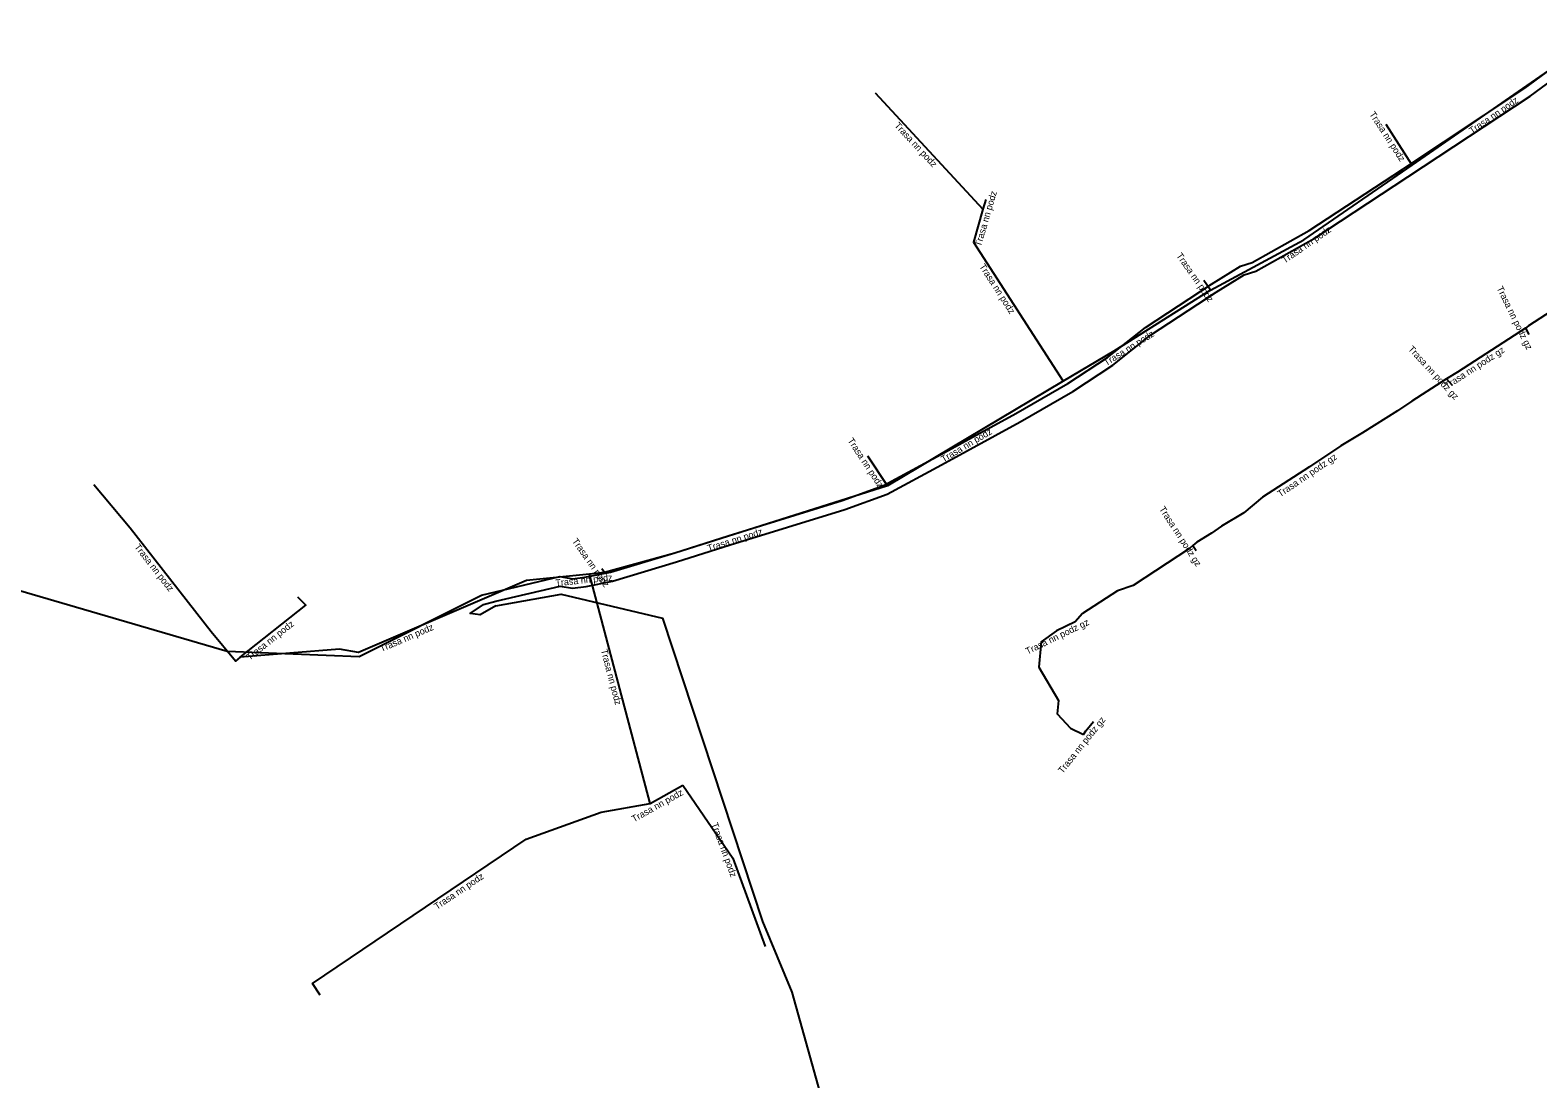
# Model space of a CAD drawing. Extents: x -711262 to -710488, y -1025222 to -1024810.
# Drawn here: x -711027.9 to -710915.5, y -1025074.1 to -1024995.9 of the extents above; entities that cross this region are included whole.
import ezdxf

# ---------------------------------------------------------------- set-up
doc = ezdxf.new("R2010")
doc.units = 0
for name, color, linetype in [('Popiskový text - Ostatní atributy Trasy', 7, 'Continuous'), ('Spojnice NN', 7, 'Continuous'), ('Spojnice VN', 7, 'Continuous')]:
    doc.layers.add(name, color=color, linetype=linetype)

msp = doc.modelspace()

# ---------------------------------------------------------------- linework, layer by layer
at = {"layer": 'Spojnice NN'}
for points in [[(-710924.81, -1025005.99), (-710911.47, -1024996.77)], [(-710964.86, -1025000.62), (-710956.82, -1025009.27)], [(-710924.81, -1025005.99), (-710926.76, -1025002.98)], [(-710939.85, -1025015.32), (-710932.89, -1025011.57), (-710924.81, -1025005.99)], [(-710899.11, -1025006.35), (-710900.09, -1025007.1), (-710905.35, -1025011.12), (-710905.55, -1025011.2), (-710906.97, -1025012.01), (-710911.93, -1025015.25), (-710916.14, -1025017.98), (-710916.36, -1025018.14)], [(-710956.61, -1025008.55), (-710956.82, -1025009.27)], [(-710956.82, -1025009.27), (-710957.52, -1025011.73), (-710950.83, -1025022.11)], [(-710939.85, -1025015.32), (-710947.06, -1025019.87), (-710950.83, -1025022.11)], [(-710939.85, -1025015.32), (-710940.35, -1025014.6)], [(-710916.36, -1025018.14), (-710921.45, -1025021.44), (-710922.25, -1025021.94)], [(-710916.36, -1025018.14), (-710916.12, -1025018.63)], [(-710950.83, -1025022.11), (-710963.95, -1025029.91)], [(-710922.25, -1025021.94), (-710924.84, -1025023.59), (-710925.92, -1025024.32), (-710928.52, -1025025.96), (-710930.15, -1025026.92), (-710932.47, -1025028.5), (-710935.98, -1025030.74), (-710937.37, -1025031.92), (-710939.03, -1025032.91), (-710939.77, -1025033.43), (-710940.87, -1025034.1), (-710941.17, -1025034.36)], [(-710922.25, -1025021.94), (-710921.84, -1025022.39)], [(-710963.95, -1025029.91), (-710965.4, -1025027.7)], [(-711012.21, -1025042.68), (-711012.54, -1025042.97), (-711014.37, -1025040.78), (-711020.41, -1025033.05), (-711023.11, -1025029.82)], [(-710963.95, -1025029.91), (-710979.79, -1025034.92), (-710985.05, -1025036.37)], [(-710941.17, -1025034.36), (-710941.41, -1025034.58), (-710945.61, -1025037.34), (-710946.8, -1025037.74), (-710949.41, -1025039.43), (-710949.95, -1025040.04), (-710951.33, -1025040.71), (-710952.48, -1025041.52), (-710952.65, -1025043.41), (-710951.2, -1025045.9), (-710951.29, -1025046.89), (-710950.3, -1025047.97), (-710949.32, -1025048.43)], [(-710941.17, -1025034.36), (-710940.93, -1025034.73)], [(-710986.15, -1025036.48), (-710990.85, -1025036.96), (-711003.39, -1025042.33), (-711004.79, -1025042.07), (-711012.21, -1025042.68)], [(-710985.05, -1025036.37), (-710986.15, -1025036.48)], [(-710981.63, -1025053.58), (-710986.15, -1025036.48)], [(-710985.05, -1025036.37), (-710985.24, -1025036.1)], [(-711012.21, -1025042.68), (-711007.3, -1025038.8), (-711007.89, -1025038.2)], [(-710949.32, -1025048.43), (-710949.14, -1025048.17), (-710948.58, -1025047.47)], [(-710981.63, -1025053.58), (-710979.19, -1025052.21)], [(-710979.19, -1025052.21), (-710975.46, -1025057.66), (-710973.06, -1025064.23)], [(-711006.23, -1025067.88), (-711006.82, -1025066.99), (-710990.88, -1025056.25), (-710985.29, -1025054.23), (-710981.63, -1025053.58)]]:
    msp.add_lwpolyline(points, dxfattribs=at)
at = {"layer": 'Spojnice VN'}
for points in [[(-710993.13, -1025038.86), (-710994.3, -1025039.53), (-710995.06, -1025039.43), (-710994.06, -1025038.74), (-710993.15, -1025038.51), (-710988.35, -1025037.39), (-710987.43, -1025037.53), (-710986.41, -1025037.41), (-710984.44, -1025037.01), (-710979.68, -1025035.58), (-710975.68, -1025034.3), (-710967.12, -1025031.66), (-710963.96, -1025030.52), (-710959.91, -1025028.34), (-710954.05, -1025025.14), (-710950.13, -1025022.88), (-710947.15, -1025020.92), (-710944.33, -1025018.68), (-710939.43, -1025015.48), (-710937.35, -1025014.18), (-710936.48, -1025013.91), (-710932.13, -1025011.48), (-710925.14, -1025006.88), (-710916.02, -1025000.85), (-710910.1, -1024996.5)], [(-710994.22, -1025038.06), (-710988.38, -1025036.67), (-710987.41, -1025036.83), (-710986.51, -1025036.72), (-710984.59, -1025036.33), (-710979.8, -1025034.89), (-710975.83, -1025033.62), (-710967.33, -1025030.99), (-710964.23, -1025029.88), (-710960.24, -1025027.71), (-710954.38, -1025024.52), (-710950.49, -1025022.28), (-710947.53, -1025020.33), (-710944.71, -1025018.09), (-710939.78, -1025014.87), (-710937.63, -1025013.52), (-710936.76, -1025013.26), (-710932.49, -1025010.88), (-710925.51, -1025006.29), (-710916.41, -1025000.27), (-710910.52, -1024995.94)], [(-711060.89, -1025028.3), (-711013.17, -1025042.23), (-711003.33, -1025042.63), (-710994.22, -1025038.06)], [(-710993.13, -1025038.86), (-710988.27, -1025037.98), (-710980.72, -1025039.77), (-710973.27, -1025062.38), (-710971.08, -1025067.64), (-710967.8, -1025079.41)]]:
    msp.add_lwpolyline(points, dxfattribs=at)

# ---------------------------------------------------------------- texts
at = {"layer": 'Popiskový text - Ostatní atributy Trasy'}
for s, rotation, p in [('Trasa nn podz', 34.6418, (-710920.36, -1025003.7)), ('Trasa nn podz', 302.9974, (-710928.04, -1025002.2)), ('Trasa nn podz', 312.9068, (-710963.46, -1025003.08)), ('Trasa nn podz', 73.7398, (-710956.97, -1025012.11)), ('Trasa nn podz', 34.643, (-710934.32, -1025013.35)), ('Trasa nn podz', 302.8021, (-710957.12, -1025013.55)), ('Trasa nn podz', 304.7778, (-710942.43, -1025012.75)), ('Trasa nn podz gz', 296.0954, (-710918.54, -1025015.17)), ('Trasa nn podz', 32.2547, (-710947.62, -1025020.99)), ('Trasa nn podz gz', 312.7307, (-710925.16, -1025019.74)), ('Trasa nn podz gz', 32.9566, (-710922.21, -1025022.71)), ('Trasa nn podz', 30.7286, (-710959.76, -1025028.18)), ('Trasa nn podz', 303.2362, (-710966.94, -1025026.53)), ('Trasa nn podz gz', 34.2562, (-710934.65, -1025030.77)), ('Trasa nn podz gz', 302.8465, (-710943.71, -1025031.63)), ('Trasa nn podz', 17.5515, (-710977.28, -1025034.81)), ('Trasa nn podz', 308.003, (-711020.12, -1025034.47)), ('Trasa nn podz', 305.1342, (-710987.49, -1025034.03)), ('Trasa nn podz', 5.7106, (-710988.67, -1025037.39)), ('Trasa nn podz', 38.3166, (-711011.49, -1025042.94)), ('Trasa nn podz', 23.182, (-711001.66, -1025042.3)), ('Trasa nn podz gz', 25.8969, (-710953.5, -1025042.49)), ('Trasa nn podz', 284.8062, (-710985.32, -1025042.15)), ('Trasa nn podz gz', 51.3402, (-710950.88, -1025051.39)), ('Trasa nn podz', 29.3131, (-710982.84, -1025055)), ('Trasa nn podz', 290.0501, (-710977.08, -1025055.11)), ('Trasa nn podz', 33.9712, (-710997.53, -1025061.52))]:
    msp.add_text(s, height=0.5, rotation=rotation, dxfattribs=at).set_placement(p)

doc.saveas('drawing.dxf')
